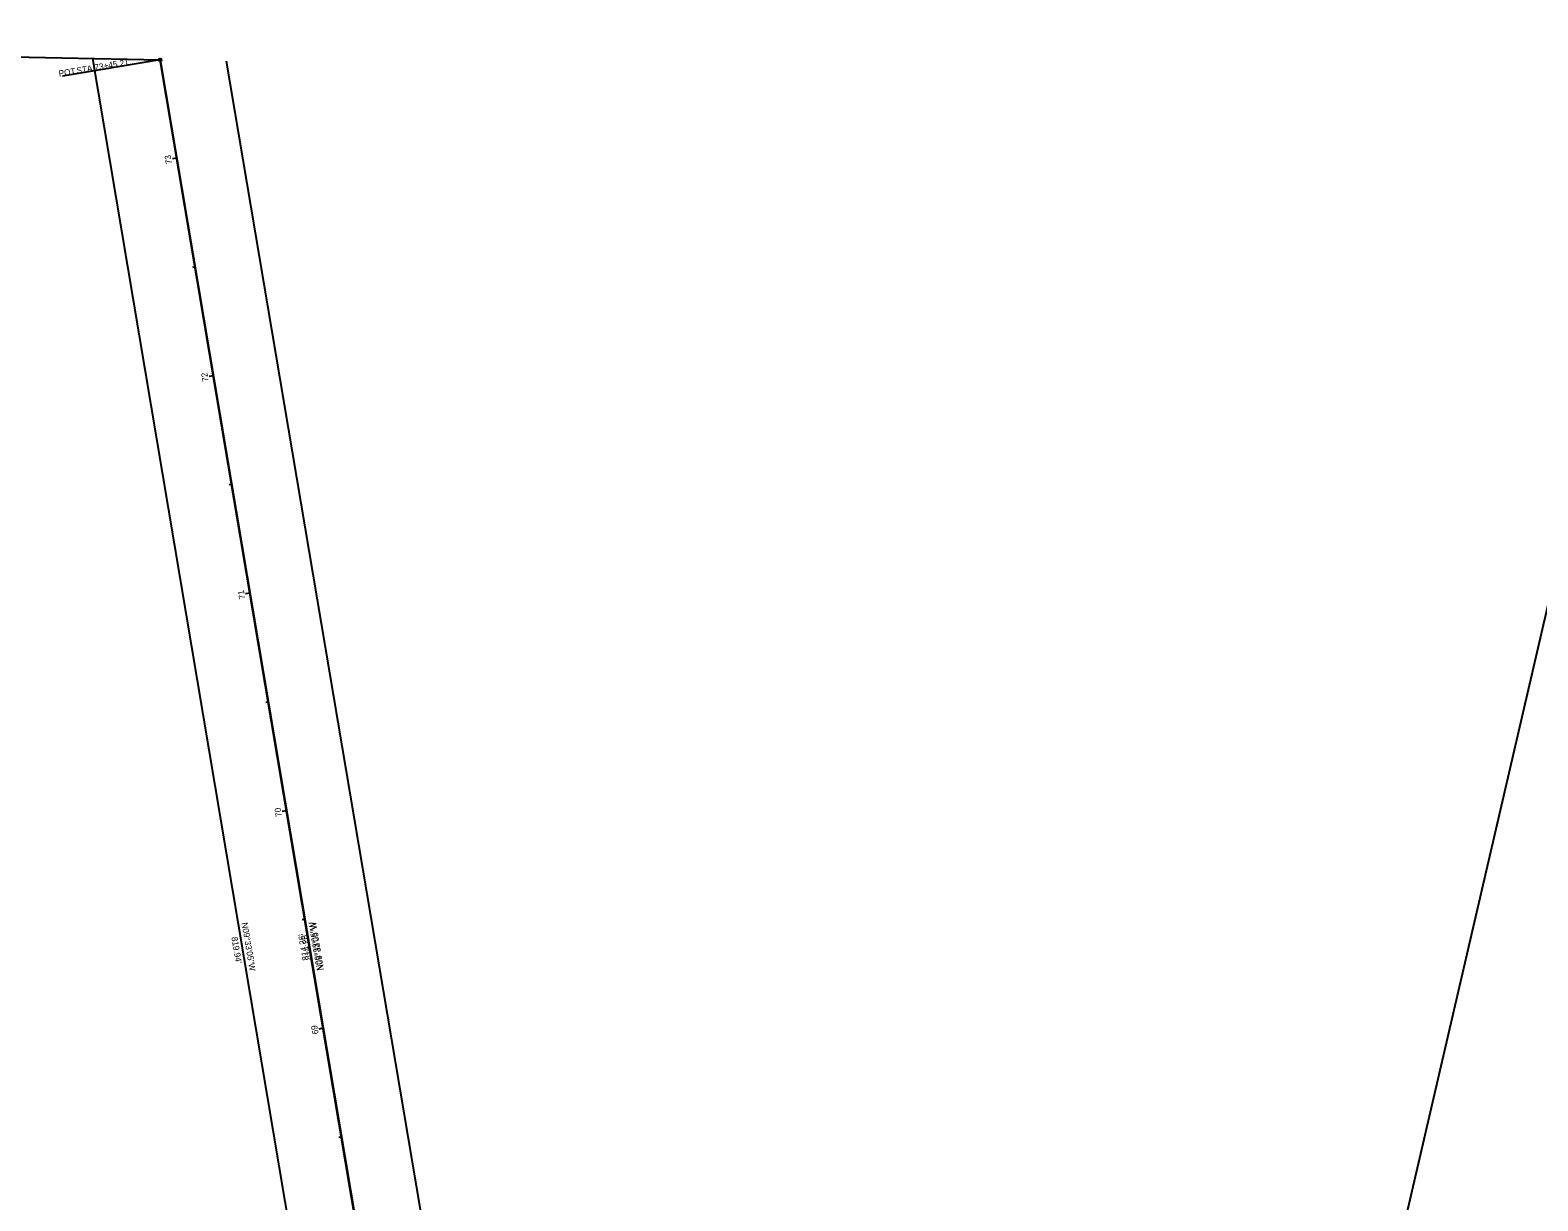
# Model space of a CAD drawing. Extents: x 2346746 to 2349554, y 247132 to 249252.
# Drawn here: x 2347467 to 2348150, y 248721 to 249252 of the extents above; entities that cross this region are included whole.
import ezdxf

# ---------------------------------------------------------------- set-up
doc = ezdxf.new("R2010")
doc.units = 0
for name, color, linetype in [('_CIVIL_CONSTRUCTION', 7, 'Continuous'), ('PF_X_Ground_Line', 7, 'Continuous'), ('UT_X_FO', 7, 'Continuous'), ('V-SURV-ANNO', 7, 'Continuous'), ('V-SURV-IPF', 7, 'Continuous'), ('V-TOPO-ANNO', 7, 'Continuous'), ('V-TOPO-BNDY', 7, 'Continuous'), ('V-UTIL-WATR-LINE-ANNO', 7, 'Continuous'), ('V-UTIL-WATR-STRC', 7, 'Continuous')]:
    doc.layers.add(name, color=color, linetype=linetype)

msp = doc.modelspace()

# ---------------------------------------------------------------- linework, layer by layer
at = {"layer": '_CIVIL_CONSTRUCTION'}
msp.add_line((2347525.54, 249238.58), (2347481.17, 249231.11), dxfattribs=at)
msp.add_circle((2347525.54, 249238.58), 0.6, dxfattribs=at)
at = {"layer": 'UT_X_FO'}
msp.add_line((2347660.65, 248435.6), (2347525.54, 249238.58), dxfattribs=at)
at = {"layer": 'V-SURV-ANNO'}
for p, q in [((2347533.04, 249193.99), (2347531.07, 249193.66)), ((2347541.34, 249144.69), (2347540.16, 249144.49)), ((2347549.64, 249095.38), (2347547.66, 249095.05)), ((2347557.93, 249046.07), (2347556.75, 249045.87)), ((2347566.23, 248996.77), (2347564.26, 248996.43)), ((2347574.53, 248947.46), (2347573.34, 248947.26)), ((2347582.82, 248898.15), (2347580.85, 248897.82)), ((2347591.12, 248848.84), (2347589.94, 248848.65)), ((2347599.42, 248799.54), (2347597.44, 248799.21)), ((2347607.71, 248750.23), (2347606.53, 248750.03))]:
    msp.add_line(p, q, dxfattribs=at)
at = {"layer": 'V-TOPO-ANNO'}
msp.add_lwpolyline([(2346864.44, 249252.04), (2347525.54, 249238.58), (2347621.59, 248667.77), (2348067.21, 248614.43), (2348211.26, 249235.08), (2349553.92, 249207.61), (2349518.11, 247171.02), (2347341.77, 247208.55)], dxfattribs=at)
at = {"layer": 'V-TOPO-BNDY'}
for p, q in [((2347631.07, 248430.63), (2347495.01, 249239.2)), ((2347677.12, 248518.55), (2347555.54, 249237.97)), ((2347677.12, 248518.55), (2347555.54, 249237.97)), ((2347677.12, 248518.55), (2347555.54, 249237.97))]:
    msp.add_line(p, q, dxfattribs=at)

# ---------------------------------------------------------------- texts
at = {"layer": '_CIVIL_CONSTRUCTION'}
for s, p in [('POT', (2347479.74, 249230.91)), (' STA. ', (2347486.77, 249232.09)), ('73+45.21', (2347495.97, 249233.64))]:
    msp.add_text(s, height=2.8, rotation=9.55135, dxfattribs=at).set_placement(p)
at = {"layer": 'PF_X_Ground_Line'}
msp.add_text('N09°33\'05"W', height=2.8, rotation=99.55135, dxfattribs=at).set_placement((2347599.83, 248826.02))
at = {"layer": 'V-SURV-ANNO'}
for s, p in [('73', (2347530.92, 249191.53)), ('72', (2347547.52, 249092.9)), ('71', (2347564.11, 248994.27)), ('70', (2347580.72, 248895.62)), ('69', (2347597.3, 248797.04))]:
    msp.add_text(s, height=2.8, rotation=99.55135, dxfattribs=at).set_placement(p)
at = {"layer": 'V-SURV-IPF'}
msp.add_text("814.26'", height=2.8, rotation=99.55135, dxfattribs=at).set_placement((2347594.13, 248830.74))
at = {"layer": 'V-UTIL-WATR-LINE-ANNO'}
for s, p in [('N09°33\'05"W', (2347599.24, 248825.92)), ("814.26'", (2347592.79, 248830.51))]:
    msp.add_text(s, height=2.8, rotation=99.55135, dxfattribs=at).set_placement(p)
at = {"layer": 'V-UTIL-WATR-STRC'}
for s, p in [('N09°33\'05"W', (2347562.38, 248847.29)), ("819.94'", (2347557.79, 248840.8))]:
    msp.add_text(s, height=2.8, rotation=279.55147, dxfattribs=at).set_placement(p)

doc.saveas('drawing.dxf')
